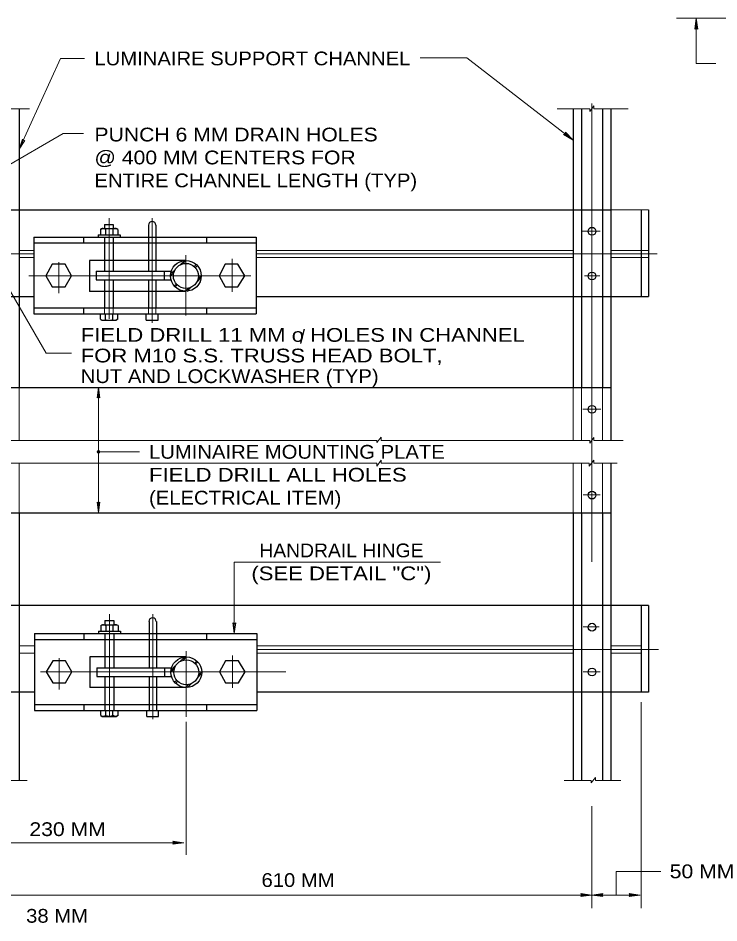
# Model space of a CAD drawing. Extents: x 312601.858 to 312602.699, y 144420.109 to 144420.704.
# Drawn here: x 312602.1105 to 312602.2633, y 144420.2466 to 144420.4439 of the extents above; entities that cross this region are included whole.
import ezdxf
from ezdxf.enums import TextEntityAlignment as Align

# ---------------------------------------------------------------- set-up
doc = ezdxf.new("R2010")
doc.units = 0
doc.header["$LTSCALE"] = 0.0012
for name, pattern in [('DOT_DASHED', [7.7, 5, -1.2, 0.3, -1.2]), ('LONG_DASHED', [7.5, 6, -1.5]), ('SHORT_DASHED', [2.7, 1.5, -1.2])]:
    doc.linetypes.add(name, pattern=pattern)
for name, color, linetype, lineweight in [('1', 7, 'Continuous', 13), ('2', 7, 'Continuous', 13), ('39', 7, 'Continuous', 13)]:
    doc.layers.add(name, color=color, linetype=linetype, lineweight=lineweight)

msp = doc.modelspace()

# ---------------------------------------------------------------- hatches: boundary and pattern name
at = {"layer": '1'}
msp.add_hatch(color=256, dxfattribs=at).paths.add_polyline_path([(312602.128283, 144420.3493, 1), (312602.127717, 144420.3493, 1)])
at = {"layer": '39'}
for points in [[(312602.2583, 144420.4417), (312602.258, 144420.4415), (312602.2583, 144420.4439), (312602.2587, 144420.4415)], [(312602.2298, 144420.4186), (312602.2298, 144420.419), (312602.2315, 144420.4173), (312602.2294, 144420.4185)], [(312602.1444, 144420.264), (312602.1442, 144420.2644), (312602.1466, 144420.264), (312602.1442, 144420.2637)], [(312602.2334, 144420.2526), (312602.2332, 144420.253), (312602.2356, 144420.2526), (312602.2332, 144420.2523)], [(312602.2378, 144420.2526), (312602.238, 144420.2523), (312602.2356, 144420.2526), (312602.238, 144420.253)], [(312602.2439, 144420.2526), (312602.2437, 144420.253), (312602.2461, 144420.2526), (312602.2437, 144420.2523)]]:
    msp.add_hatch(color=256, dxfattribs=at).paths.add_polyline_path(points)

# ---------------------------------------------------------------- linework, layer by layer
at = {"layer": '1'}
for p, q in [((312602.254, 144420.4439), (312602.293, 144420.4439)), ((312602.2583, 144420.4439), (312602.2583, 144420.434)), ((312602.1197, 144420.4351), (312602.1249, 144420.4351)), ((312602.1981, 144420.4352), (312602.2083, 144420.4352)), ((312602.2626, 144420.434), (312602.2583, 144420.434)), ((312602.1071, 144420.4241), (312602.1129, 144420.4241)), ((312602.228, 144420.4241), (312602.2351, 144420.4241)), ((312602.2351, 144420.4235), (312602.236, 144420.4248)), ((312602.2351, 144420.4235), (312602.2351, 144420.4241)), ((312602.236, 144420.4241), (312602.236, 144420.4248)), ((312602.236, 144420.4241), (312602.2435, 144420.4241)), ((312602.1073, 144420.4112), (312602.1203, 144420.4187)), ((312602.1203, 144420.4187), (312602.1247, 144420.4187)), ((312602.2397, 144420.4021), (312602.2479, 144420.4021)), ((312602.1458, 144420.3901), (312602.1468, 144420.391)), ((312602.1464, 144420.3904), (312602.1471, 144420.391)), ((312602.1489, 144420.3897), (312602.1493, 144420.3902)), ((312602.1437, 144420.3881), (312602.1447, 144420.389)), ((312602.1437, 144420.3877), (312602.1444, 144420.3884)), ((312602.1491, 144420.3895), (312602.1496, 144420.3899)), ((312602.1072, 144420.387), (312602.1166, 144420.3708)), ((312602.1495, 144420.3864), (312602.1504, 144420.3873)), ((312602.1497, 144420.387), (312602.1504, 144420.3877)), ((312602.1445, 144420.3855), (312602.145, 144420.3859)), ((312602.1447, 144420.3853), (312602.1452, 144420.3858)), ((312602.1469, 144420.3843), (312602.1476, 144420.385)), ((312602.1473, 144420.3843), (312602.1482, 144420.3853)), ((312602.1284, 144420.3782), (312602.1287, 144420.378)), ((312602.128, 144420.3633), (312602.128, 144420.336)), ((312602.1071, 144420.3518), (312602.1887, 144420.3518)), ((312602.1887, 144420.3513), (312602.1896, 144420.3525)), ((312602.1887, 144420.3513), (312602.1887, 144420.3518)), ((312602.1896, 144420.3518), (312602.1896, 144420.3525)), ((312602.1896, 144420.3518), (312602.2033, 144420.3518)), ((312602.2033, 144420.3518), (312602.2351, 144420.3518)), ((312602.2351, 144420.3512), (312602.236, 144420.3524)), ((312602.2351, 144420.3512), (312602.2351, 144420.3518)), ((312602.236, 144420.3518), (312602.236, 144420.3524)), ((312602.236, 144420.3518), (312602.2424, 144420.3518)), ((312602.128, 144420.3493), (312602.1369, 144420.3493)), ((312602.1071, 144420.3468), (312602.1887, 144420.3468)), ((312602.1887, 144420.3462), (312602.1896, 144420.3475)), ((312602.1887, 144420.3462), (312602.1887, 144420.3468)), ((312602.1896, 144420.3468), (312602.1896, 144420.3475)), ((312602.1896, 144420.3468), (312602.2038, 144420.3468)), ((312602.2033, 144420.3468), (312602.235, 144420.3468)), ((312602.235, 144420.3462), (312602.236, 144420.3475)), ((312602.235, 144420.3462), (312602.235, 144420.3468)), ((312602.236, 144420.3468), (312602.236, 144420.3475)), ((312602.236, 144420.3468), (312602.2411, 144420.3468)), ((312602.1459, 144420.3037), (312602.1469, 144420.3046)), ((312602.1465, 144420.3039), (312602.1472, 144420.3046)), ((312602.149, 144420.3032), (312602.1494, 144420.3037)), ((312602.1492, 144420.3031), (312602.1497, 144420.3035)), ((312602.1438, 144420.3017), (312602.1447, 144420.3026)), ((312602.1438, 144420.3013), (312602.1445, 144420.302)), ((312602.1498, 144420.3006), (312602.1505, 144420.3013)), ((312602.1446, 144420.2991), (312602.1451, 144420.2995)), ((312602.1448, 144420.2988), (312602.1453, 144420.2993)), ((312602.1496, 144420.3), (312602.1504, 144420.3009)), ((312602.147, 144420.2979), (312602.1477, 144420.2986)), ((312602.1474, 144420.2979), (312602.1483, 144420.2988)), ((312602.2463, 144420.2947), (312602.2463, 144420.2498)), ((312602.1074, 144420.2776), (312602.1124, 144420.2776)), ((312602.2295, 144420.2776), (312602.2354, 144420.2776)), ((312602.2354, 144420.2771), (312602.2364, 144420.2783)), ((312602.2354, 144420.2771), (312602.2354, 144420.2776)), ((312602.2364, 144420.2776), (312602.2364, 144420.2783)), ((312602.2364, 144420.2776), (312602.2419, 144420.2776)), ((312602.1471, 144420.2727), (312602.1471, 144420.2614)), ((312602.2356, 144420.272), (312602.2356, 144420.2498))]:
    msp.add_line(p, q, dxfattribs=at)
at = {"layer": '1', "lineweight": 25}
for p, q in [((312602.1107, 144420.4241), (312602.1107, 144420.3633)), ((312602.2315, 144420.4241), (312602.2315, 144420.3633)), ((312602.2333, 144420.4241), (312602.2333, 144420.3633)), ((312602.2379, 144420.4241), (312602.2379, 144420.3633)), ((312602.2397, 144420.4241), (312602.2397, 144420.3518)), ((312602.1107, 144420.4021), (312602.2315, 144420.4021)), ((312602.2463, 144420.4021), (312602.2463, 144420.3832)), ((312602.2479, 144420.4021), (312602.2479, 144420.3832)), ((312602.1284, 144420.3978), (312602.1287, 144420.398)), ((312602.1287, 144420.398), (312602.1318, 144420.398)), ((312602.1293, 144420.3989), (312602.1312, 144420.3989)), ((312602.1293, 144420.3989), (312602.1293, 144420.398)), ((312602.1312, 144420.3989), (312602.1312, 144420.398)), ((312602.1322, 144420.3978), (312602.1318, 144420.398)), ((312602.1389, 144420.3988), (312602.1389, 144420.3961)), ((312602.1405, 144420.3988), (312602.1405, 144420.3961)), ((312602.1139, 144420.3961), (312602.1624, 144420.3961)), ((312602.1139, 144420.3961), (312602.1139, 144420.3794)), ((312602.1247, 144420.3961), (312602.1247, 144420.3949)), ((312602.1279, 144420.3966), (312602.1279, 144420.3961)), ((312602.1279, 144420.3966), (312602.1327, 144420.3966)), ((312602.1284, 144420.3978), (312602.1284, 144420.3966)), ((312602.1295, 144420.3978), (312602.1295, 144420.3966)), ((312602.1311, 144420.3978), (312602.1311, 144420.3966)), ((312602.1322, 144420.3978), (312602.1322, 144420.3966)), ((312602.1327, 144420.3966), (312602.1327, 144420.3961)), ((312602.1515, 144420.3961), (312602.1515, 144420.3949)), ((312602.1624, 144420.3961), (312602.1624, 144420.3794)), ((312602.1139, 144420.3949), (312602.1624, 144420.3949)), ((312602.1293, 144420.3949), (312602.1293, 144420.391)), ((312602.1312, 144420.3949), (312602.1312, 144420.391)), ((312602.1389, 144420.3949), (312602.1389, 144420.391)), ((312602.1405, 144420.3949), (312602.1405, 144420.391)), ((312602.126, 144420.391), (312602.126, 144420.3843)), ((312602.147, 144420.391), (312602.126, 144420.391)), ((312602.1275, 144420.3887), (312602.1275, 144420.3868)), ((312602.1275, 144420.3887), (312602.1438, 144420.3887)), ((312602.1423, 144420.3887), (312602.1423, 144420.3868)), ((312602.1275, 144420.3868), (312602.1438, 144420.3868)), ((312602.147, 144420.3843), (312602.126, 144420.3843)), ((312602.1293, 144420.3843), (312602.1293, 144420.3807)), ((312602.1312, 144420.3843), (312602.1312, 144420.3807)), ((312602.1389, 144420.3843), (312602.1389, 144420.3807)), ((312602.1405, 144420.3843), (312602.1405, 144420.3807)), ((312602.1107, 144420.3832), (312602.1139, 144420.3832)), ((312602.1624, 144420.3832), (312602.2315, 144420.3832)), ((312602.2397, 144420.3832), (312602.2479, 144420.3832)), ((312602.1139, 144420.3807), (312602.1624, 144420.3807)), ((312602.1247, 144420.3807), (312602.1247, 144420.3794)), ((312602.1515, 144420.3807), (312602.1515, 144420.3794)), ((312602.1139, 144420.3794), (312602.1624, 144420.3794)), ((312602.1284, 144420.3782), (312602.1284, 144420.3794)), ((312602.1295, 144420.3782), (312602.1295, 144420.3794)), ((312602.1311, 144420.3782), (312602.1311, 144420.3794)), ((312602.1322, 144420.3782), (312602.1318, 144420.378)), ((312602.1322, 144420.3782), (312602.1322, 144420.3794)), ((312602.1384, 144420.378), (312602.1384, 144420.3793)), ((312602.141, 144420.378), (312602.141, 144420.3794)), ((312602.1287, 144420.378), (312602.1318, 144420.378)), ((312602.1384, 144420.378), (312602.141, 144420.378)), ((312602.1025, 144420.3633), (312602.2397, 144420.3633)), ((312602.2397, 144420.3468), (312602.2397, 144420.2776)), ((312602.1025, 144420.336), (312602.2397, 144420.336)), ((312602.1107, 144420.336), (312602.1107, 144420.2776)), ((312602.2315, 144420.336), (312602.2315, 144420.2776)), ((312602.2333, 144420.336), (312602.2333, 144420.2776)), ((312602.2379, 144420.336), (312602.2379, 144420.2776)), ((312602.2315, 144420.3158), (312602.1107, 144420.3158)), ((312602.2479, 144420.3158), (312602.2397, 144420.3158)), ((312602.2463, 144420.3158), (312602.2463, 144420.2969)), ((312602.2479, 144420.3158), (312602.2479, 144420.2969)), ((312602.1285, 144420.3114), (312602.1288, 144420.3116)), ((312602.1285, 144420.3114), (312602.1285, 144420.3102)), ((312602.1288, 144420.3116), (312602.1319, 144420.3116)), ((312602.1294, 144420.3125), (312602.1313, 144420.3125)), ((312602.1294, 144420.3125), (312602.1294, 144420.3116)), ((312602.1296, 144420.3114), (312602.1296, 144420.3102)), ((312602.1311, 144420.3114), (312602.1311, 144420.3102)), ((312602.1313, 144420.3125), (312602.1313, 144420.3116)), ((312602.1323, 144420.3114), (312602.1319, 144420.3116)), ((312602.1323, 144420.3114), (312602.1323, 144420.3102)), ((312602.139, 144420.3123), (312602.139, 144420.3097)), ((312602.1406, 144420.3123), (312602.1406, 144420.3097)), ((312602.114, 144420.3097), (312602.1625, 144420.3097)), ((312602.114, 144420.3097), (312602.114, 144420.2929)), ((312602.1248, 144420.3097), (312602.1248, 144420.3084)), ((312602.128, 144420.3102), (312602.128, 144420.3097)), ((312602.128, 144420.3102), (312602.1328, 144420.3102)), ((312602.1328, 144420.3102), (312602.1328, 144420.3097)), ((312602.1515, 144420.3097), (312602.1515, 144420.3084)), ((312602.1625, 144420.3097), (312602.1625, 144420.2929)), ((312602.114, 144420.3084), (312602.1625, 144420.3084)), ((312602.1294, 144420.3084), (312602.1294, 144420.3046)), ((312602.1313, 144420.3084), (312602.1313, 144420.3046)), ((312602.139, 144420.3084), (312602.139, 144420.3046)), ((312602.1406, 144420.3084), (312602.1406, 144420.3046)), ((312602.1261, 144420.3046), (312602.1261, 144420.2979)), ((312602.1471, 144420.3046), (312602.1261, 144420.3046)), ((312602.1276, 144420.3022), (312602.1276, 144420.3003)), ((312602.1276, 144420.3022), (312602.1439, 144420.3022)), ((312602.1424, 144420.3022), (312602.1424, 144420.3003)), ((312602.1276, 144420.3003), (312602.1439, 144420.3003)), ((312602.1471, 144420.2979), (312602.1261, 144420.2979)), ((312602.1294, 144420.2979), (312602.1294, 144420.2942)), ((312602.1313, 144420.2979), (312602.1313, 144420.2942)), ((312602.139, 144420.2979), (312602.139, 144420.2942)), ((312602.1406, 144420.2979), (312602.1406, 144420.2942)), ((312602.114, 144420.2969), (312602.1107, 144420.2969)), ((312602.2315, 144420.2969), (312602.1625, 144420.2969)), ((312602.2479, 144420.2969), (312602.2397, 144420.2969)), ((312602.114, 144420.2942), (312602.1625, 144420.2942)), ((312602.1248, 144420.2942), (312602.1248, 144420.2929)), ((312602.1515, 144420.2942), (312602.1515, 144420.2929)), ((312602.114, 144420.2929), (312602.1625, 144420.2929)), ((312602.1285, 144420.2918), (312602.1285, 144420.2929)), ((312602.1285, 144420.2918), (312602.1288, 144420.2916)), ((312602.1288, 144420.2916), (312602.1319, 144420.2916)), ((312602.1296, 144420.2918), (312602.1296, 144420.2929)), ((312602.1311, 144420.2918), (312602.1311, 144420.2929)), ((312602.1323, 144420.2918), (312602.1319, 144420.2916)), ((312602.1323, 144420.2918), (312602.1323, 144420.2929)), ((312602.1385, 144420.2916), (312602.1385, 144420.2929)), ((312602.1385, 144420.2916), (312602.1411, 144420.2916)), ((312602.1411, 144420.2916), (312602.1411, 144420.2929))]:
    msp.add_line(p, q, dxfattribs=at)
at = {"layer": '1', "linetype": 'DOT_DASHED'}
for p, q in [((312602.2356, 144420.4253), (312602.2356, 144420.275)), ((312602.1303, 144420.4003), (312602.1303, 144420.3783)), ((312602.1397, 144420.4003), (312602.1397, 144420.3774)), ((312602.0265, 144420.3925), (312602.1139, 144420.3925)), ((312602.147, 144420.3922), (312602.147, 144420.379)), ((312602.1624, 144420.3925), (312602.2498, 144420.3925)), ((312602.1193, 144420.3907), (312602.1193, 144420.3839)), ((312602.1571, 144420.3914), (312602.1571, 144420.3844)), ((312602.1571, 144420.3907), (312602.1571, 144420.3842)), ((312602.1128, 144420.3877), (312602.1612, 144420.3877)), ((312602.234, 144420.3877), (312602.2373, 144420.3877)), ((312602.2336, 144420.3586), (312602.2375, 144420.3586)), ((312602.2337, 144420.3399), (312602.2374, 144420.3399)), ((312602.1304, 144420.3139), (312602.1304, 144420.2918)), ((312602.1398, 144420.3139), (312602.1398, 144420.291)), ((312602.2337, 144420.3111), (312602.2372, 144420.3111)), ((312601.9291, 144420.3062), (312602.114, 144420.3062)), ((312602.1471, 144420.3058), (312602.1471, 144420.2915)), ((312602.1625, 144420.3062), (312602.2501, 144420.3062)), ((312602.1194, 144420.3043), (312602.1194, 144420.2975)), ((312602.1572, 144420.3049), (312602.1572, 144420.298)), ((312602.1572, 144420.3043), (312602.1572, 144420.2978)), ((312602.1153, 144420.3013), (312602.1688, 144420.3013)), ((312602.2337, 144420.3013), (312602.2374, 144420.3013))]:
    msp.add_line(p, q, dxfattribs=at)
at = {"layer": '1', "linetype": 'LONG_DASHED', "lineweight": 25}
for p, q in [((312602.1025, 144420.4021), (312602.1107, 144420.4021)), ((312602.2315, 144420.4021), (312602.2397, 144420.4021)), ((312602.1025, 144420.3832), (312602.1107, 144420.3832)), ((312602.2315, 144420.3832), (312602.2397, 144420.3832)), ((312602.1107, 144420.3158), (312602.1025, 144420.3158)), ((312602.2397, 144420.3158), (312602.2315, 144420.3158)), ((312602.1107, 144420.2969), (312602.1025, 144420.2969)), ((312602.2397, 144420.2969), (312602.2315, 144420.2969))]:
    msp.add_line(p, q, dxfattribs=at)
at = {"layer": '1', "linetype": 'SHORT_DASHED', "lineweight": 25}
for p, q in [((312602.1293, 144420.3961), (312602.1293, 144420.3949)), ((312602.1312, 144420.3961), (312602.1312, 144420.3949)), ((312602.1389, 144420.3961), (312602.1389, 144420.3949)), ((312602.1405, 144420.3961), (312602.1405, 144420.3949)), ((312602.1293, 144420.391), (312602.1293, 144420.3887)), ((312602.1312, 144420.391), (312602.1312, 144420.3887)), ((312602.1389, 144420.391), (312602.1389, 144420.3887)), ((312602.1405, 144420.391), (312602.1405, 144420.3887)), ((312602.1293, 144420.3868), (312602.1293, 144420.3843)), ((312602.1312, 144420.3868), (312602.1312, 144420.3843)), ((312602.1389, 144420.3868), (312602.1389, 144420.3843)), ((312602.1405, 144420.3868), (312602.1405, 144420.3843)), ((312602.1294, 144420.3097), (312602.1294, 144420.3084)), ((312602.1313, 144420.3097), (312602.1313, 144420.3084)), ((312602.139, 144420.3097), (312602.139, 144420.3084)), ((312602.1406, 144420.3097), (312602.1406, 144420.3084)), ((312602.1294, 144420.3046), (312602.1294, 144420.3022)), ((312602.1313, 144420.3046), (312602.1313, 144420.3022)), ((312602.139, 144420.3046), (312602.139, 144420.3022)), ((312602.1406, 144420.3046), (312602.1406, 144420.3022)), ((312602.1294, 144420.3003), (312602.1294, 144420.2979)), ((312602.1313, 144420.3003), (312602.1313, 144420.2979)), ((312602.139, 144420.3003), (312602.139, 144420.2979)), ((312602.1406, 144420.3003), (312602.1406, 144420.2979)), ((312602.1294, 144420.2942), (312602.1294, 144420.2929)), ((312602.1313, 144420.2942), (312602.1313, 144420.2929)), ((312602.139, 144420.2942), (312602.139, 144420.2929)), ((312602.1406, 144420.2942), (312602.1406, 144420.2929))]:
    msp.add_line(p, q, dxfattribs=at)
at = {"layer": '1', "linetype": 'LONG_DASHED'}
for p, q in [((312602.1107, 144420.3932), (312602.1139, 144420.3932)), ((312602.1624, 144420.3932), (312602.2315, 144420.3932)), ((312602.2397, 144420.3932), (312602.2479, 144420.3932)), ((312602.1107, 144420.3917), (312602.1139, 144420.3917)), ((312602.1624, 144420.3917), (312602.2315, 144420.3917)), ((312602.2397, 144420.3917), (312602.2479, 144420.3917)), ((312602.1107, 144420.3633), (312602.1107, 144420.3518)), ((312602.2315, 144420.3633), (312602.2315, 144420.3518)), ((312602.2333, 144420.3633), (312602.2333, 144420.3518)), ((312602.2379, 144420.3633), (312602.2379, 144420.3518)), ((312602.1107, 144420.3468), (312602.1107, 144420.336)), ((312602.2315, 144420.3468), (312602.2315, 144420.336)), ((312602.2333, 144420.3468), (312602.2333, 144420.336)), ((312602.2379, 144420.3468), (312602.2379, 144420.336)), ((312602.1107, 144420.307), (312602.114, 144420.307)), ((312602.1107, 144420.3054), (312602.114, 144420.3054)), ((312602.1625, 144420.307), (312602.2315, 144420.307)), ((312602.1625, 144420.3054), (312602.2315, 144420.3054)), ((312602.2397, 144420.307), (312602.2463, 144420.307)), ((312602.2397, 144420.3054), (312602.2463, 144420.3054))]:
    msp.add_line(p, q, dxfattribs=at)
at = {"layer": '1', "linetype": 'SHORT_DASHED'}
for p, q in [((312602.1293, 144420.3807), (312602.1293, 144420.3794)), ((312602.1312, 144420.3807), (312602.1312, 144420.3794)), ((312602.1389, 144420.3807), (312602.1389, 144420.3794)), ((312602.1405, 144420.3807), (312602.1405, 144420.3794))]:
    msp.add_line(p, q, dxfattribs=at)
at = {"layer": '1'}
for points in [[(312602.1119, 144420.4172), (312602.1107, 144420.4153), (312602.1114, 144420.4175), (312602.1115, 144420.4171)], [(312602.1277, 144420.3611), (312602.128, 144420.3633), (312602.1283, 144420.3611), (312602.128, 144420.3613)], [(312602.1283, 144420.3383), (312602.128, 144420.336), (312602.1277, 144420.3383), (312602.128, 144420.338)], [(312602.1579, 144420.312), (312602.1576, 144420.3097), (312602.1573, 144420.312), (312602.1576, 144420.3117)]]:
    msp.add_lwpolyline(points, close=True, dxfattribs=at)
at = {"layer": '1', "linetype": 'DOT_DASHED'}
msp.add_lwpolyline([(312602.2335, 144420.3974), (312602.2336, 144420.3974), (312602.2374, 144420.3974)], dxfattribs=at)
at = {"layer": '1', "lineweight": 25}
for points in [[(312602.1179, 144420.3853), (312602.1207, 144420.3853), (312602.1221, 144420.3877), (312602.1207, 144420.3902), (312602.1179, 144420.3902), (312602.1165, 144420.3877)], [(312602.1556, 144420.3853), (312602.1584, 144420.3853), (312602.1599, 144420.3877), (312602.1584, 144420.3902), (312602.1556, 144420.3902), (312602.1543, 144420.3877)], [(312602.118, 144420.2989), (312602.1208, 144420.2989), (312602.1222, 144420.3013), (312602.1208, 144420.3037), (312602.118, 144420.3037), (312602.1166, 144420.3013)], [(312602.1557, 144420.2989), (312602.1585, 144420.2989), (312602.16, 144420.3013), (312602.1585, 144420.3037), (312602.1557, 144420.3037), (312602.1544, 144420.3013)]]:
    msp.add_lwpolyline(points, close=True, dxfattribs=at)
at = {"layer": '1'}
for points in [[(312602.2026, 144420.3252), (312602.1576, 144420.3252), (312602.1576, 144420.3097)], [(312602.1471, 144420.2904), (312602.1471, 144420.2727), (312602.1471, 144420.2704)], [(312602.0154, 144420.264), (312602.0985, 144420.264), (312602.1466, 144420.264)], [(312602.1066, 144420.2526), (312602.2356, 144420.2526), (312602.2461, 144420.2526)]]:
    msp.add_lwpolyline(points, dxfattribs=at)
at = {"layer": '1', "lineweight": 25}
for centre, radius in [((312602.23561, 144420.39741), 0.00085), ((312602.14704, 144420.387677), 0.003357), ((312602.14704, 144420.387677), 0.00272), ((312602.23561, 144420.387635), 0.00085), ((312602.23561, 144420.358565), 0.00085), ((312602.23561, 144420.339865), 0.00085), ((312602.23561, 144420.31105), 0.00085), ((312602.147125, 144420.301233), 0.003357), ((312602.147125, 144420.301233), 0.00272), ((312602.23561, 144420.301275), 0.00085)]:
    msp.add_circle(centre, radius, dxfattribs=at)
at = {"layer": '1'}
msp.add_circle((312602.128, 144420.3493), 0.000283, dxfattribs=at)
at = {"layer": '1', "lineweight": 25}
for centre, radius, start, end in [((312602.128935, 144420.39707), 0.000936, 53.82173, 116.36509), ((312602.130253, 144420.396199), 0.001806, 64.94239, 115.05762), ((312602.13157, 144420.39707), 0.000936, 63.63491, 126.17827), ((312602.139688, 144420.398727), 0.000812, 0, 180), ((312602.128935, 144420.378923), 0.000936, 243.63491, 306.17827), ((312602.13157, 144420.378923), 0.000936, 233.82173, 296.36509), ((312602.139773, 144420.312283), 0.000812, 0, 180), ((312602.12902, 144420.310625), 0.000936, 53.82173, 116.36509), ((312602.130338, 144420.309754), 0.001806, 64.94239, 115.05762), ((312602.131655, 144420.310625), 0.000936, 63.63491, 126.17827), ((312602.12902, 144420.292577), 0.000936, 243.63491, 306.17827), ((312602.130338, 144420.293449), 0.001806, 244.94238, 295.05761)]:
    msp.add_arc(centre, radius, start, end, dxfattribs=at)
at = {"layer": '1'}
msp.add_arc((312602.130253, 144420.379794), 0.001806, 244.94238, 295.05761, dxfattribs=at)
at = {"layer": '1', "lineweight": 25}
msp.add_ellipse((312602.131655, 144420.292577), major_axis=(0.000935, 0.000043), ratio=0.963008, start_param=4.0355358, end_param=5.359486, dxfattribs=at)
at = {"layer": '2'}
for p, q in [((312602.1107, 144420.4153), (312602.1197, 144420.4351)), ((312602.2083, 144420.4352), (312602.2315, 144420.4173)), ((312602.1221, 144420.3708), (312602.1166, 144420.3708)), ((312602.2409, 144420.2526), (312602.2409, 144420.2578)), ((312602.2506, 144420.2578), (312602.2409, 144420.2578))]:
    msp.add_line(p, q, dxfattribs=at)
at = {"layer": '39'}
for points in [[(312602.2583, 144420.4417), (312602.258, 144420.4415), (312602.2583, 144420.4439), (312602.2587, 144420.4415)], [(312602.2298, 144420.4186), (312602.2298, 144420.419), (312602.2315, 144420.4173), (312602.2294, 144420.4185)], [(312602.1444, 144420.264), (312602.1442, 144420.2644), (312602.1466, 144420.264), (312602.1442, 144420.2637)], [(312602.2334, 144420.2526), (312602.2332, 144420.253), (312602.2356, 144420.2526), (312602.2332, 144420.2523)], [(312602.2378, 144420.2526), (312602.238, 144420.2523), (312602.2356, 144420.2526), (312602.238, 144420.253)], [(312602.2439, 144420.2526), (312602.2437, 144420.253), (312602.2461, 144420.2526), (312602.2437, 144420.2523)]]:
    msp.add_lwpolyline(points, close=True, dxfattribs=at)

# ---------------------------------------------------------------- texts
at = {"layer": '1'}
for s, width, p in [('LUMINAIRE SUPPORT CHANNEL ', 1.1, (312602.1271, 144420.4336)), ('FIELD DRILL 11 MM o HOLES IN CHANNEL', 1.2, (312602.1241, 144420.3733)), ('FOR M10 S.S. TRUSS HEAD BOLT,', 1.2, (312602.1241, 144420.3688)), ('NUT AND LOCKWASHER (TYP)', 1.1, (312602.1241, 144420.3643))]:
    msp.add_text(s, height=0.003, dxfattribs=dict(at, width=width)).set_placement(p)
at = {"layer": '2'}
for s, width, p in [('PUNCH 6 MM DRAIN HOLES', 1.15, (312602.1271, 144420.417)), ('@ 400 MM CENTERS FOR', 1.15, (312602.1271, 144420.412)), ('ENTIRE CHANNEL LENGTH (TYP)', 1.1, (312602.1271, 144420.407)), ('LUMINAIRE MOUNTING PLATE', 1.1, (312602.139, 144420.3478)), ('FIELD DRILL ALL HOLES', 1.2, (312602.139, 144420.3428)), ('(ELECTRICAL ITEM)', 1.1, (312602.139, 144420.3378))]:
    msp.add_text(s, height=0.003, dxfattribs=dict(at, width=width)).set_placement(p)
msp.add_text('/', height=0.003, dxfattribs=at).set_placement((312602.17245, 144420.3729), align=Align.CENTER)
for s, width, p in [('HANDRAIL HINGE', 1.05, (312602.18095, 144420.3263)), ('(SEE DETAIL "C")', 1.2, (312602.18095, 144420.3213)), ('230 MM', 1.15, (312602.12125, 144420.2655)), ('50 MM', 1.15, (312602.2596, 144420.2563)), ('610 MM', 1.1, (312602.1715, 144420.2544)), ('38 MM', 1.1, (312602.11895, 144420.2466))]:
    msp.add_text(s, height=0.003, dxfattribs=dict(at, width=width)).set_placement(p, align=Align.CENTER)

doc.saveas('drawing.dxf')
